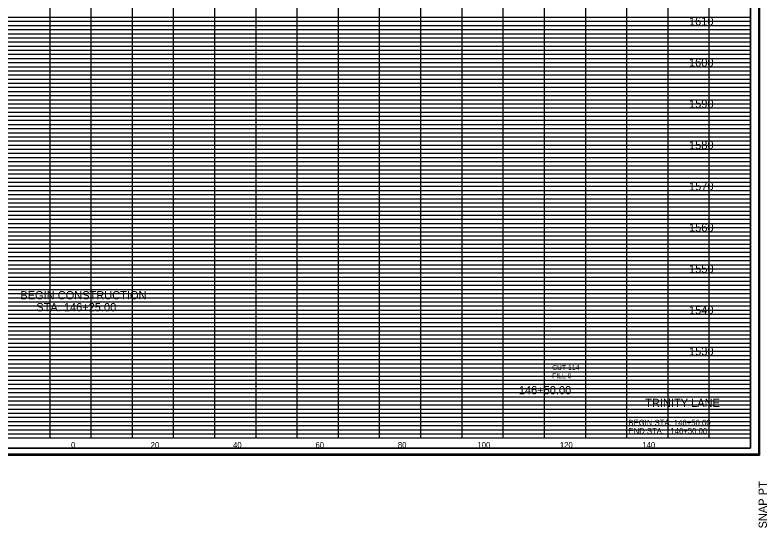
# Model space of a CAD drawing. Extents: x 980 to 1380, y 1248 to 3387.
# Drawn here: x 1141.5 to 1324, y 1518.2 to 1642.5 of the extents above; entities that cross this region are included whole.
import ezdxf

# ---------------------------------------------------------------- set-up
doc = ezdxf.new("R2010")
doc.units = 0
for name, color, linetype in [('DESIGN - SHEET - Corner Text', 7, 'Continuous'), ('DESIGN - SHEET - Light Grid', 7, 'Continuous'), ('DESIGN - SHEET - Linework', 7, 'Continuous'), ('DESIGN - SHEET - Plot Shape', 7, 'Continuous'), ('DESIGN - TYPICAL - Text', 7, 'Continuous')]:
    doc.layers.add(name, color=color, linetype=linetype)

# ---------------------------------------------------------------- blocks, each defined once
blk = doc.blocks.new('XSTSHT')
at = {"layer": 'DESIGN - SHEET - Light Grid'}
for p, q in [((8, 10.2), (16, 10.2)), ((8, 10.1), (16, 10.1)), ((16, 10.2), (24, 10.2)), ((16, 10.1), (24, 10.1)), ((24, 10.2), (32, 10.2)), ((24, 10.1), (32, 10.1)), ((8, 9.9), (16, 9.9)), ((16, 9.9), (24, 9.9)), ((24, 9.9), (32, 9.9)), ((8, 9.8), (16, 9.8)), ((8, 9.7), (16, 9.7)), ((16, 9.8), (24, 9.8)), ((16, 9.7), (24, 9.7)), ((24, 9.8), (32, 9.8)), ((24, 9.7), (32, 9.7)), ((8, 9.6), (16, 9.6)), ((8, 9.5), (16, 9.5)), ((16, 9.6), (24, 9.6)), ((16, 9.5), (24, 9.5)), ((24, 9.6), (32, 9.6)), ((24, 9.5), (32, 9.5)), ((8, 9.4), (16, 9.4)), ((16, 9.4), (24, 9.4)), ((24, 9.4), (32, 9.4)), ((8, 9.3), (16, 9.3)), ((8, 9.2), (16, 9.2)), ((16, 9.3), (24, 9.3)), ((16, 9.2), (24, 9.2)), ((24, 9.3), (32, 9.3)), ((24, 9.2), (32, 9.2)), ((8, 9.1), (16, 9.1)), ((16, 9.1), (24, 9.1)), ((24, 9.1), (32, 9.1)), ((8, 8.9), (16, 8.9)), ((8, 8.8), (16, 8.8)), ((16, 8.9), (24, 8.9)), ((16, 8.8), (24, 8.8)), ((24, 8.9), (32, 8.9)), ((24, 8.8), (32, 8.8)), ((8, 8.7), (16, 8.7)), ((8, 8.6), (16, 8.6)), ((16, 8.7), (24, 8.7)), ((16, 8.6), (24, 8.6)), ((24, 8.7), (32, 8.7)), ((24, 8.6), (32, 8.6)), ((8, 8.5), (16, 8.5)), ((8, 8.4), (16, 8.4)), ((16, 8.5), (24, 8.5)), ((16, 8.4), (24, 8.4)), ((24, 8.5), (32, 8.5)), ((24, 8.4), (32, 8.4)), ((8, 8.3), (16, 8.3)), ((16, 8.3), (24, 8.3)), ((24, 8.3), (32, 8.3)), ((8, 8.2), (16, 8.2)), ((8, 8.1), (16, 8.1)), ((16, 8.2), (24, 8.2)), ((16, 8.1), (24, 8.1)), ((24, 8.2), (32, 8.2)), ((24, 8.1), (32, 8.1)), ((8, 7.9), (16, 7.9)), ((16, 7.9), (24, 7.9)), ((24, 7.9), (32, 7.9)), ((8, 7.8), (16, 7.8)), ((8, 7.7), (16, 7.7)), ((16, 7.8), (24, 7.8)), ((16, 7.7), (24, 7.7)), ((24, 7.8), (32, 7.8)), ((24, 7.7), (32, 7.7)), ((8, 7.6), (16, 7.6)), ((8, 7.5), (16, 7.5)), ((16, 7.6), (24, 7.6)), ((16, 7.5), (24, 7.5)), ((24, 7.6), (32, 7.6)), ((24, 7.5), (32, 7.5)), ((8, 7.4), (16, 7.4)), ((8, 7.3), (16, 7.3)), ((16, 7.4), (24, 7.4)), ((16, 7.3), (24, 7.3)), ((24, 7.4), (32, 7.4)), ((24, 7.3), (32, 7.3)), ((8, 7.2), (16, 7.2)), ((16, 7.2), (24, 7.2)), ((24, 7.2), (32, 7.2)), ((8, 7.1), (16, 7.1)), ((16, 7.1), (24, 7.1)), ((24, 7.1), (32, 7.1)), ((8, 6.9), (16, 6.9)), ((8, 6.8), (16, 6.8)), ((16, 6.9), (24, 6.9)), ((16, 6.8), (24, 6.8)), ((24, 6.9), (32, 6.9)), ((24, 6.8), (32, 6.8)), ((8, 6.7), (16, 6.7)), ((8, 6.6), (16, 6.6)), ((16, 6.7), (24, 6.7)), ((16, 6.6), (24, 6.6)), ((24, 6.7), (32, 6.7)), ((24, 6.6), (32, 6.6)), ((8, 6.5), (16, 6.5)), ((8, 6.4), (16, 6.4)), ((16, 6.5), (24, 6.5)), ((16, 6.4), (24, 6.4)), ((24, 6.5), (32, 6.5)), ((24, 6.4), (32, 6.4)), ((8, 6.3), (16, 6.3)), ((16, 6.3), (24, 6.3)), ((24, 6.3), (32, 6.3)), ((8, 6.2), (16, 6.2)), ((8, 6.1), (16, 6.1)), ((16, 6.2), (24, 6.2)), ((16, 6.1), (24, 6.1)), ((24, 6.2), (32, 6.2)), ((24, 6.1), (32, 6.1)), ((8, 5.9), (16, 5.9)), ((16, 5.9), (24, 5.9)), ((24, 5.9), (32, 5.9)), ((8, 5.8), (16, 5.8)), ((8, 5.7), (16, 5.7)), ((16, 5.8), (24, 5.8)), ((16, 5.7), (24, 5.7)), ((24, 5.8), (32, 5.8)), ((24, 5.7), (32, 5.7)), ((8, 5.6), (16, 5.6)), ((8, 5.5), (16, 5.5)), ((16, 5.6), (24, 5.6)), ((16, 5.5), (24, 5.5)), ((24, 5.6), (32, 5.6)), ((24, 5.5), (32, 5.5)), ((8, 5.4), (16, 5.4)), ((8, 5.3), (16, 5.3)), ((16, 5.4), (24, 5.4)), ((16, 5.3), (24, 5.3)), ((24, 5.4), (32, 5.4)), ((24, 5.3), (32, 5.3)), ((8, 5.2), (16, 5.2)), ((16, 5.2), (24, 5.2)), ((24, 5.2), (32, 5.2)), ((8, 5.1), (16, 5.1)), ((16, 5.1), (24, 5.1)), ((24, 5.1), (32, 5.1)), ((8, 4.9), (16, 4.9)), ((8, 4.8), (16, 4.8)), ((16, 4.9), (24, 4.9)), ((16, 4.8), (24, 4.8)), ((24, 4.9), (32, 4.9)), ((24, 4.8), (32, 4.8)), ((8, 4.7), (16, 4.7)), ((8, 4.6), (16, 4.6)), ((16, 4.7), (24, 4.7)), ((16, 4.6), (24, 4.6)), ((24, 4.7), (32, 4.7)), ((24, 4.6), (32, 4.6)), ((8, 4.5), (16, 4.5)), ((8, 4.4), (16, 4.4)), ((16, 4.5), (24, 4.5)), ((16, 4.4), (24, 4.4)), ((24, 4.5), (32, 4.5)), ((24, 4.4), (32, 4.4)), ((8, 4.3), (16, 4.3)), ((8, 4.2), (16, 4.2)), ((16, 4.3), (24, 4.3)), ((16, 4.2), (24, 4.2)), ((24, 4.3), (32, 4.3)), ((24, 4.2), (32, 4.2)), ((8, 4.1), (16, 4.1)), ((16, 4.1), (24, 4.1)), ((24, 4.1), (32, 4.1)), ((8, 3.9), (16, 3.9)), ((16, 3.9), (24, 3.9)), ((24, 3.9), (32, 3.9)), ((8, 3.8), (16, 3.8)), ((8, 3.7), (16, 3.7)), ((16, 3.8), (24, 3.8)), ((16, 3.7), (24, 3.7)), ((24, 3.8), (32, 3.8)), ((24, 3.7), (32, 3.7)), ((8, 3.6), (16, 3.6)), ((8, 3.5), (16, 3.5)), ((16, 3.6), (24, 3.6)), ((16, 3.5), (24, 3.5)), ((24, 3.6), (32, 3.6)), ((24, 3.5), (32, 3.5)), ((8, 3.4), (16, 3.4)), ((8, 3.3), (16, 3.3)), ((16, 3.4), (24, 3.4)), ((16, 3.3), (24, 3.3)), ((24, 3.4), (32, 3.4)), ((24, 3.3), (32, 3.3)), ((8, 3.2), (16, 3.2)), ((16, 3.2), (24, 3.2)), ((24, 3.2), (32, 3.2)), ((8, 3.1), (16, 3.1)), ((16, 3.1), (24, 3.1)), ((24, 3.1), (32, 3.1)), ((8, 2.9), (16, 2.9)), ((8, 2.8), (16, 2.8)), ((16, 2.9), (24, 2.9)), ((16, 2.8), (24, 2.8)), ((24, 2.9), (32, 2.9)), ((24, 2.8), (32, 2.8)), ((8, 2.7), (16, 2.7)), ((8, 2.6), (16, 2.6)), ((16, 2.7), (24, 2.7)), ((16, 2.6), (24, 2.6)), ((24, 2.7), (32, 2.7)), ((24, 2.6), (32, 2.6)), ((8, 2.5), (16, 2.5)), ((8, 2.4), (16, 2.4)), ((16, 2.5), (24, 2.5)), ((16, 2.4), (24, 2.4)), ((24, 2.5), (32, 2.5)), ((24, 2.4), (32, 2.4)), ((8, 2.3), (16, 2.3)), ((8, 2.2), (16, 2.2)), ((16, 2.3), (24, 2.3)), ((16, 2.2), (24, 2.2)), ((24, 2.3), (32, 2.3)), ((24, 2.2), (32, 2.2)), ((8, 2.1), (16, 2.1)), ((16, 2.1), (24, 2.1)), ((24, 2.1), (32, 2.1)), ((8, 1.9), (16, 1.9)), ((16, 1.9), (24, 1.9)), ((24, 1.9), (32, 1.9)), ((8, 1.8), (16, 1.8)), ((8, 1.7), (16, 1.7)), ((16, 1.8), (24, 1.8)), ((16, 1.7), (24, 1.7)), ((24, 1.8), (32, 1.8)), ((24, 1.7), (32, 1.7)), ((8, 1.6), (16, 1.6)), ((8, 1.5), (16, 1.5)), ((16, 1.6), (24, 1.6)), ((16, 1.5), (24, 1.5)), ((24, 1.6), (32, 1.6)), ((24, 1.5), (32, 1.5)), ((8, 1.4), (16, 1.4)), ((8, 1.3), (16, 1.3)), ((16, 1.4), (24, 1.4)), ((16, 1.3), (24, 1.3)), ((24, 1.4), (32, 1.4)), ((24, 1.3), (32, 1.3)), ((8, 1.2), (16, 1.2)), ((8, 1.1), (16, 1.1)), ((16, 1.2), (24, 1.2)), ((16, 1.1), (24, 1.1)), ((24, 1.2), (32, 1.2)), ((24, 1.1), (32, 1.1)), ((8, 0.9), (16, 0.9)), ((8, 0.8), (16, 0.8)), ((16, 0.9), (24, 0.9)), ((16, 0.8), (24, 0.8)), ((24, 0.9), (32, 0.9)), ((24, 0.8), (32, 0.8)), ((8, 0.7), (16, 0.7)), ((8, 0.6), (16, 0.6)), ((16, 0.7), (24, 0.7)), ((16, 0.6), (24, 0.6)), ((24, 0.7), (32, 0.7)), ((24, 0.6), (32, 0.6)), ((8, 0.5), (16, 0.5)), ((8, 0.4), (16, 0.4)), ((16, 0.5), (24, 0.5)), ((16, 0.4), (24, 0.4)), ((24, 0.5), (32, 0.5)), ((24, 0.4), (32, 0.4)), ((8, 0.3), (16, 0.3)), ((8, 0.2), (16, 0.2)), ((16, 0.3), (24, 0.3)), ((16, 0.2), (24, 0.2)), ((24, 0.3), (32, 0.3)), ((24, 0.2), (32, 0.2)), ((8, 0.1), (16, 0.1)), ((16, 0.1), (24, 0.1)), ((24, 0.1), (32, 0.1))]:
    blk.add_line(p, q, dxfattribs=at)
at = {"layer": 'DESIGN - SHEET - Linework'}
for p, q in [((32.217, 21.414), (32.217, -0.414)), ((15, 0), (15, 21)), ((16, 0), (16, 21)), ((17, 0), (17, 21)), ((18, 0), (18, 21)), ((19, 0), (19, 21)), ((20, 0), (20, 21)), ((21, 0), (21, 21)), ((22, 0), (22, 21)), ((23, 0), (23, 21)), ((24, 0), (24, 21)), ((25, 0), (25, 21)), ((26, 0), (26, 21)), ((27, 0), (27, 21)), ((28, 0), (28, 20)), ((29, 0), (29, 20)), ((30, 0), (30, 20)), ((31, 0), (31, 20)), ((0, 10), (32, 10)), ((0, 9), (32, 9)), ((0, 8), (32, 8)), ((0, 7), (32, 7)), ((0, 6), (32, 6)), ((0, 5), (32, 5)), ((0, 4), (32, 4)), ((0, 3), (32, 3)), ((0, 2), (32, 2)), ((0, 1), (32, 1)), ((-1.823, -0.414), (32.217, -0.414))]:
    blk.add_line(p, q, dxfattribs=at)
blk.add_lwpolyline([(0, 21), (0, 0), (32, 0), (32, 21), (0, 21)], dxfattribs=at)
at = {"layer": 'DESIGN - SHEET - Plot Shape'}
for points in [[(-1.803, 21.394), (32.197, 21.394), (32.197, -0.394), (-1.803, -0.394)], [(-0.85, 21), (32, 21), (32, -0.25), (-0.85, -0.25)]]:
    blk.add_lwpolyline(points, close=True, dxfattribs=at)
at = {"layer": 'DESIGN - SHEET - Corner Text'}
blk.add_text('SNAP PT  ', height=0.2, rotation=90, dxfattribs=at).set_placement((32.397, -2.194))

msp = doc.modelspace()

# ---------------------------------------------------------------- linework, layer by layer
at = {"layer": 'DESIGN - SHEET - Plot Shape'}
msp.add_lwpolyline([(991.5, 1537.5), (1320, 1537.5), (1320, 1750), (991.5, 1750)], close=True, dxfattribs=at)

# ---------------------------------------------------------------- block references
at = {"layer": 'DESIGN - TYPICAL - Text', "xscale": 10, "yscale": 10}
msp.add_blockref('XSTSHT', (1000, 1540), dxfattribs=at)

# ---------------------------------------------------------------- texts
at = {"layer": 'DESIGN - SHEET - Corner Text'}
for s, height, p in [('TRINITY LANE', 2, (1294.45, 1547.5)), ('BEGIN STA. 146+50.00', 1.4, (1290.38, 1543)), ('END STA.   146+50.00', 1.4, (1290.38, 1541))]:
    msp.add_text(s, height=height, dxfattribs=at).set_placement(p)
at = {"layer": 'DESIGN - TYPICAL - Text'}
for s, height, p in [('     1610     ', 2, (1301.37, 1640)), ('     1600     ', 2, (1301.37, 1630)), ('     1590     ', 2, (1301.37, 1620)), ('     1580     ', 2, (1301.37, 1610)), ('     1570     ', 2, (1301.37, 1600)), ('     1560     ', 2, (1301.37, 1590)), ('     1550     ', 2, (1301.37, 1580)), ('BEGIN CONSTRUCTION', 2, (1142.8, 1573.59)), ('STA. 146+25.00', 2, (1146.67, 1570.69)), ('     1540     ', 2, (1301.37, 1570)), ('     1530     ', 2, (1301.37, 1560)), ('CUT 114', 1.2, (1271.85, 1556.47)), ('FILL 0', 1.2, (1271.85, 1554.47)), ('     146+50.00     ', 2, (1260.06, 1550.58)), ('     0     ', 1.4, (1152.51, 1537.6)), ('     0     ', 1.4, (1152.51, 1537.6)), ('     20     ', 1.4, (1171.82, 1537.6)), ('     40     ', 1.4, (1191.82, 1537.6)), ('     60     ', 1.4, (1211.82, 1537.6)), ('     80     ', 1.4, (1231.82, 1537.6)), ('     100     ', 1.4, (1251.14, 1537.6)), ('     120     ', 1.4, (1271.14, 1537.6)), ('     140     ', 1.4, (1291.14, 1537.6))]:
    msp.add_text(s, height=height, dxfattribs=at).set_placement(p)

doc.saveas('drawing.dxf')
